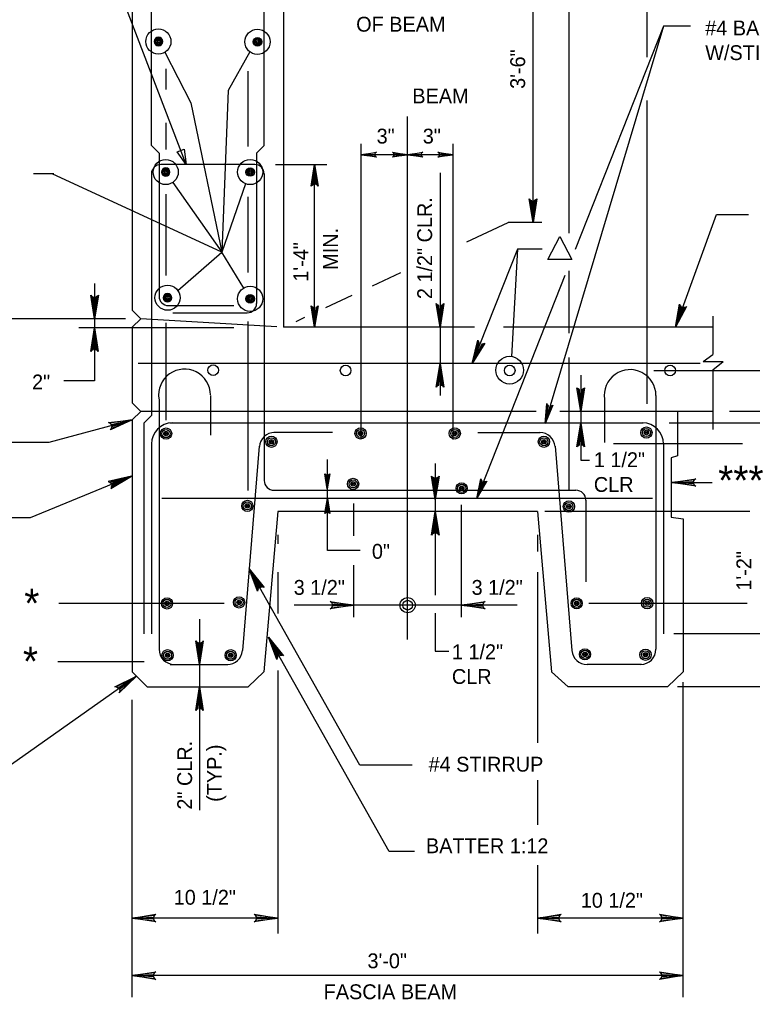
# Model space of a CAD drawing. Extents: x 642009 to 642864, y 298232 to 300014.
# Drawn here: x 642137.3 to 642285.5, y 298530.4 to 298728.5 of the extents above; entities that cross this region are included whole.
import ezdxf

# ---------------------------------------------------------------- set-up
doc = ezdxf.new("R2010")
doc.units = 0
for name, color, linetype in [('1', 7, 'Continuous'), ('15', 7, 'Continuous'), ('2', 7, 'Continuous'), ('22', 7, 'Continuous'), ('50', 7, 'Continuous')]:
    doc.layers.add(name, color=color, linetype=linetype)

# ---------------------------------------------------------------- blocks, each defined once
blk = doc.blocks.new('BAR')
at = {"layer": '50'}
for radius in [2, 1.5, 1, 0.5]:
    blk.add_circle((0, 0), radius, dxfattribs=at)

msp = doc.modelspace()

# ---------------------------------------------------------------- linework, layer by layer
at = {"layer": '1'}
for p, q in [((642227.71, 298683.59), (642236.08, 298687.5)), ((642237.99, 298682.07), (642228.8, 298659)), ((642237.99, 298682.07), (642236.75, 298660.42)), ((642208.66, 298674.71), (642214.36, 298677.37)), ((642199.22, 298670.31), (642204.57, 298672.8)), ((642193.2, 298667.5), (642195, 298668.34))]:
    msp.add_line(p, q, dxfattribs=at)
for points in [[(642241.68, 298692.04), (642241.35, 298691.87), (642241.11, 298687.5), (642241.68, 298692.04), (642241.87, 298692.27), (642241.11, 298687.5), (642240.89, 298691.86), (642240.56, 298692.02), (642241.11, 298687.5), (642240.35, 298692.27), (642240.56, 298692.02)], [(642153.04, 298672.57), (642152.71, 298672.41), (642152.47, 298668.03), (642153.04, 298672.57), (642153.24, 298672.81), (642152.47, 298668.03), (642152.25, 298672.4), (642151.93, 298672.56), (642152.47, 298668.03), (642151.71, 298672.81), (642151.93, 298672.56)], [(642222.89, 298670.85), (642222.56, 298670.68), (642222.32, 298666.31), (642222.89, 298670.85), (642223.09, 298671.09), (642222.32, 298666.31), (642222.1, 298670.68), (642221.78, 298670.84), (642222.32, 298666.31), (642221.56, 298671.09), (642221.78, 298670.84)], [(642151.9, 298661.65), (642152.23, 298661.81), (642152.47, 298666.19), (642151.9, 298661.65), (642151.7, 298661.41), (642152.47, 298666.19), (642152.69, 298661.82), (642153.01, 298661.66), (642152.47, 298666.19), (642153.23, 298661.41), (642153.01, 298661.66)], [(642231.11, 298662.95), (642230.74, 298662.92), (642228.8, 298659), (642231.11, 298662.95), (642231.38, 298663.08), (642228.8, 298659), (642230.32, 298663.1), (642230.08, 298663.37), (642228.8, 298659), (642229.98, 298663.69), (642230.08, 298663.37)], [(642221.75, 298654.46), (642222.08, 298654.63), (642222.32, 298659), (642221.75, 298654.46), (642221.55, 298654.23), (642222.32, 298659), (642222.53, 298654.63), (642222.86, 298654.47), (642222.32, 298659), (642223.08, 298654.23), (642222.86, 298654.47)], [(642251.32, 298653.85), (642250.99, 298653.68), (642250.75, 298649.31), (642251.32, 298653.85), (642251.52, 298654.09), (642250.75, 298649.31), (642250.53, 298653.68), (642250.21, 298653.84), (642250.75, 298649.31), (642249.99, 298654.09), (642250.21, 298653.84)], [(642250.18, 298642.37), (642250.51, 298642.53), (642250.75, 298646.91), (642250.18, 298642.37), (642249.98, 298642.13), (642250.75, 298646.91), (642250.96, 298642.54), (642251.29, 298642.38), (642250.75, 298646.91), (642251.51, 298642.13), (642251.29, 298642.38)], [(642155.92, 298633.96), (642155.95, 298634.33), (642159.91, 298636.21), (642155.92, 298633.96), (642155.78, 298633.69), (642159.91, 298636.21), (642155.78, 298634.75), (642155.51, 298634.99), (642159.91, 298636.21), (642155.2, 298635.1), (642155.51, 298634.99)], [(642221.92, 298636.01), (642221.59, 298635.84), (642221.35, 298631.47), (642221.92, 298636.01), (642222.12, 298636.24), (642221.35, 298631.47), (642221.14, 298635.84), (642220.81, 298636), (642221.35, 298631.47), (642220.59, 298636.24), (642220.81, 298636)], [(642273.76, 298634.36), (642273.59, 298634.69), (642269.22, 298634.93), (642273.76, 298634.36), (642273.99, 298634.16), (642269.22, 298634.93), (642273.58, 298635.15), (642273.74, 298635.47), (642269.22, 298634.93), (642273.99, 298635.69), (642273.74, 298635.47)], [(642220.78, 298624.52), (642221.11, 298624.69), (642221.35, 298629.06), (642220.78, 298624.52), (642220.58, 298624.29), (642221.35, 298629.06), (642221.57, 298624.69), (642221.89, 298624.54), (642221.35, 298629.06), (642222.11, 298624.29), (642221.89, 298624.54)], [(642185.48, 298613.26), (642185.68, 298613.56), (642183.75, 298617.49), (642185.48, 298613.26), (642185.42, 298612.96), (642183.75, 298617.49), (642186.08, 298613.79), (642186.44, 298613.81), (642183.75, 298617.49), (642186.75, 298613.71), (642186.44, 298613.81)], [(642200.35, 298610.7), (642200.52, 298610.38), (642204.89, 298610.13), (642200.35, 298610.7), (642200.11, 298610.9), (642204.89, 298610.13), (642200.52, 298609.92), (642200.36, 298609.59), (642204.89, 298610.13), (642200.11, 298609.38), (642200.36, 298609.59)], [(642231.18, 298609.56), (642231.01, 298609.89), (642226.64, 298610.13), (642231.18, 298609.56), (642231.41, 298609.36), (642226.64, 298610.13), (642231.01, 298610.35), (642231.17, 298610.68), (642226.64, 298610.13), (642231.41, 298610.89), (642231.17, 298610.68)], [(642189.37, 298599.45), (642189.58, 298599.76), (642187.64, 298603.69), (642189.37, 298599.45), (642189.31, 298599.15), (642187.64, 298603.69), (642189.97, 298599.99), (642190.33, 298600.01), (642187.64, 298603.69), (642190.64, 298599.9), (642190.33, 298600.01)], [(642174.26, 298602.67), (642173.93, 298602.5), (642173.69, 298598.13), (642174.26, 298602.67), (642174.46, 298602.9), (642173.69, 298598.13), (642173.48, 298602.49), (642173.15, 298602.65), (642173.69, 298598.13), (642172.94, 298602.9), (642173.15, 298602.65)], [(642156.91, 298593.6), (642157.23, 298593.43), (642160.94, 298595.76), (642156.91, 298593.6), (642156.6, 298593.63), (642160.94, 298595.76), (642157.5, 298593.06), (642157.56, 298592.7), (642160.94, 298595.76), (642157.48, 298592.38), (642157.56, 298592.7)], [(642173.12, 298589.08), (642173.45, 298589.25), (642173.69, 298593.63), (642173.12, 298589.08), (642172.92, 298588.85), (642173.69, 298593.63), (642173.91, 298589.26), (642174.23, 298589.1), (642173.69, 298593.63), (642174.45, 298588.85), (642174.23, 298589.1)], [(642164.62, 298546.31), (642164.45, 298546.64), (642160.08, 298546.88), (642164.62, 298546.31), (642164.85, 298546.11), (642160.08, 298546.88), (642164.44, 298547.09), (642164.6, 298547.42), (642160.08, 298546.88), (642164.85, 298547.64), (642164.6, 298547.42)], [(642184.97, 298547.45), (642185.14, 298547.12), (642189.51, 298546.88), (642184.97, 298547.45), (642184.74, 298547.65), (642189.51, 298546.88), (642185.15, 298546.66), (642184.99, 298546.34), (642189.51, 298546.88), (642184.74, 298546.12), (642184.99, 298546.34)], [(642246.55, 298546.31), (642246.38, 298546.64), (642242.01, 298546.88), (642246.55, 298546.31), (642246.79, 298546.11), (642242.01, 298546.88), (642246.38, 298547.09), (642246.54, 298547.42), (642242.01, 298546.88), (642246.79, 298547.64), (642246.54, 298547.42)], [(642266.91, 298547.45), (642267.08, 298547.12), (642271.45, 298546.88), (642266.91, 298547.45), (642266.68, 298547.65), (642271.45, 298546.88), (642267.08, 298546.66), (642266.92, 298546.34), (642271.45, 298546.88), (642266.68, 298546.12), (642266.92, 298546.34)], [(642164.62, 298534.67), (642164.45, 298535), (642160.08, 298535.24), (642164.62, 298534.67), (642164.85, 298534.47), (642160.08, 298535.24), (642164.44, 298535.46), (642164.6, 298535.78), (642160.08, 298535.24), (642164.85, 298536), (642164.6, 298535.78)], [(642266.91, 298535.81), (642267.08, 298535.48), (642271.45, 298535.24), (642266.91, 298535.81), (642266.68, 298536.01), (642271.45, 298535.24), (642267.08, 298535.02), (642266.92, 298534.7), (642271.45, 298535.24), (642266.68, 298534.48), (642266.92, 298534.7)]]:
    msp.add_lwpolyline(points, dxfattribs=at)
msp.add_lwpolyline([(642244.11, 298679.99), (642246.52, 298684.68), (642248.93, 298679.99)], close=True, dxfattribs=at)
for centre, radius in [((642165.38, 298724.07), 2.54), ((642185.4, 298724.02), 2.54), ((642166.86, 298697.69), 2.54), ((642183.93, 298697.69), 2.54), ((642167.23, 298672.28), 2.54), ((642183.93, 298672.06), 2.54), ((642236.39, 298657.64), 2.8), ((642176.44, 298657.64), 1.08), ((642203.23, 298657.57), 1.08), ((642236.4, 298657.57), 1.08), ((642268.82, 298657.57), 1.08), ((642215.76, 298610.13), 1.53), ((642215.76, 298610.13), 0.983)]:
    msp.add_circle(centre, radius, dxfattribs=at)
at = {"layer": '15'}
for p, q in [((642165.5, 298651.76), (642165.5, 298601.22)), ((642265.96, 298652.52), (642265.96, 298601.22)), ((642162.43, 298646.92), (642163.97, 298648.49)), ((642162.43, 298646.92), (642162.43, 298604.35))]:
    msp.add_line(p, q, dxfattribs=at)
at = {"layer": '2'}
for p, q in [((642160.07, 298771.67), (642160.07, 298669.76)), ((642190.65, 298771.5), (642190.65, 298666.31)), ((642163.97, 298703.05), (642163.97, 298767.05)), ((642186.76, 298703.05), (642186.76, 298767.05)), ((642264.14, 298750.64), (642264.14, 298720.9)), ((642170.97, 298699.21), (642153.94, 298743.88)), ((642248.32, 298738.81), (642248.32, 298685.35)), ((642241.11, 298687.5), (642241.11, 298731.74)), ((642267.51, 298727.19), (642243.99, 298648.41)), ((642267.51, 298727.19), (642249.64, 298682)), ((642272.91, 298727.19), (642267.51, 298727.19)), ((642166.86, 298718.54), (642166.86, 298714.37)), ((642183.48, 298718.11), (642183.48, 298702.86)), ((642264.14, 298712.16), (642264.14, 298650.83)), ((642215.76, 298603.21), (642215.76, 298708.92)), ((642166.86, 298707.65), (642166.86, 298702.26)), ((642160.08, 298705.6), (642160.08, 298669.76)), ((642163.97, 298703.05), (642165.5, 298701.51)), ((642186.76, 298703.05), (642185.22, 298701.51)), ((642206.39, 298643.89), (642206.39, 298703.41)), ((642224.95, 298643.59), (642224.95, 298703.41)), ((642165.5, 298701.51), (642165.5, 298672.58)), ((642185.22, 298701.51), (642185.22, 298671.12)), ((642206.39, 298701.2), (642206.39, 298701.2)), ((642224.95, 298701.2), (642206.39, 298701.2)), ((642224.95, 298701.2), (642224.95, 298701.2)), ((642189.04, 298699.21), (642199.45, 298699.21)), ((642196.96, 298666.31), (642196.96, 298699.21)), ((642144.27, 298697.32), (642140.14, 298697.32)), ((642178.17, 298681.46), (642143.87, 298697.32)), ((642163.97, 298697.32), (642163.97, 298648.49)), ((642186.76, 298697.32), (642186.76, 298635.36)), ((642222.32, 298697.51), (642222.32, 298652.52)), ((642168.29, 298695.59), (642178.17, 298681.46)), ((642183, 298695.32), (642178.17, 298681.46)), ((642166.86, 298693.22), (642166.86, 298676.78)), ((642183.48, 298692.67), (642183.48, 298677.38)), ((642270.77, 298668.68), (642278.18, 298689.08)), ((642278.18, 298689.08), (642284.67, 298689.08)), ((642242.87, 298687.5), (642236.08, 298687.5)), ((642169.32, 298673.74), (642178.17, 298681.46)), ((642182.63, 298674.24), (642178.17, 298681.46)), ((642242.96, 298682.07), (642237.99, 298682.07)), ((642248.32, 298677.74), (642248.32, 298665.12)), ((642152.47, 298675.18), (642152.47, 298655.51)), ((642247.57, 298676.77), (642229.76, 298631.7)), ((642160.08, 298669.76), (642161.8, 298668.03)), ((642167.38, 298670.7), (642180.64, 298670.7)), ((642168.27, 298669.24), (642183.34, 298669.24)), ((642158.72, 298668.03), (642082.96, 298668.03)), ((642161.8, 298668.03), (642160.08, 298666.31)), ((642189.3, 298666.39), (642161.8, 298668.03)), ((642166.86, 298667.18), (642166.86, 298647.55)), ((642183.48, 298667.48), (642183.48, 298633.32)), ((642277.44, 298668.56), (642277.44, 298660.8)), ((642180.64, 298666.19), (642149.32, 298666.19)), ((642160.08, 298666.31), (642160.08, 298651.03)), ((642229.31, 298666.31), (642190.65, 298666.31)), ((642277.44, 298666.31), (642235.17, 298666.31)), ((642248.32, 298660.21), (642248.32, 298633.32)), ((642275.47, 298659.41), (642277.47, 298660.8)), ((642275.47, 298659.41), (642279.53, 298659.41)), ((642277.47, 298657.73), (642279.53, 298659.41)), ((642274.89, 298659), (642161.32, 298659)), ((642297.41, 298657.5), (642265.51, 298657.5)), ((642277.44, 298657.73), (642277.44, 298645.67)), ((642152.47, 298655.51), (642146.24, 298655.51)), ((642250.75, 298656.64), (642250.75, 298646.91)), ((642175.9, 298652.52), (642175.9, 298644.51)), ((642255.56, 298651.76), (642255.56, 298642.99)), ((642160.08, 298651.03), (642161.8, 298649.31)), ((642161.8, 298649.31), (642160.08, 298647.59)), ((642241.74, 298649.31), (642161.8, 298649.31)), ((642277.44, 298649.31), (642246.53, 298649.31)), ((642270.33, 298649.31), (642270.33, 298640.31)), ((642335.23, 298649.31), (642280.82, 298649.31)), ((642160.08, 298647.59), (642160.08, 298596.63)), ((642263.39, 298646.91), (642167.71, 298646.91)), ((642250.75, 298646.91), (642250.75, 298639.46)), ((642288.58, 298646.91), (642268.61, 298646.91)), ((642200.56, 298645.03), (642188.72, 298645.03)), ((642229.96, 298645.03), (642242.52, 298645.03)), ((642163.97, 298642.73), (642163.97, 298604.35)), ((642185.78, 298642.26), (642182.39, 298600.94)), ((642245.56, 298642.28), (642248.95, 298600.94)), ((642283.43, 298642.72), (642257.39, 298642.72)), ((642267.49, 298642.73), (642267.49, 298604.35)), ((642199.55, 298630.71), (642199.55, 298639.58)), ((642270.33, 298640.31), (642269.01, 298639.94)), ((642269.01, 298639.94), (642269.01, 298627.94)), ((642221.35, 298638.8), (642221.35, 298629.06)), ((642159.91, 298636.21), (642139.47, 298627.77)), ((642188.76, 298633.36), (642249.78, 298633.36)), ((642269.22, 298634.93), (642277.29, 298634.93)), ((642251.78, 298631.36), (642251.78, 298614.83)), ((642199.55, 298621.16), (642199.55, 298630.71)), ((642204.89, 298624.14), (642204.89, 298630.69)), ((642226.64, 298624.69), (642226.64, 298630.39)), ((642139.47, 298627.77), (642092.33, 298627.77)), ((642189.51, 298629.06), (642186.7, 298596.63)), ((642242.01, 298629.06), (642189.51, 298629.06)), ((642221.35, 298629.06), (642221.35, 298612.14)), ((642242.01, 298629.06), (642244.83, 298596.63)), ((642284.92, 298629.06), (642243.49, 298629.06)), ((642269.01, 298627.94), (642271.45, 298627.56)), ((642271.45, 298627.56), (642271.45, 298596.63)), ((642189.51, 298624.38), (642189.51, 298622.51)), ((642226.64, 298607.7), (642226.64, 298624.69)), ((642242.01, 298624.38), (642242.01, 298621.01)), ((642206.19, 298621.16), (642199.55, 298621.16)), ((642204.89, 298607.7), (642204.89, 298618.2)), ((642206.12, 298577.78), (642183.75, 298617.49)), ((642189.51, 298616.81), (642189.51, 298608.44)), ((642242.01, 298616.81), (642242.01, 298582.3)), ((642178.64, 298610.5), (642145.26, 298610.5)), ((642204.89, 298610.13), (642192.83, 298610.13)), ((642215.76, 298610.13), (642204.89, 298610.13)), ((642226.64, 298610.13), (642215.76, 298610.13)), ((642237.91, 298610.13), (642226.64, 298610.13)), ((642273.33, 298610.5), (642252.4, 298610.5)), ((642284.39, 298610.5), (642272.2, 298610.5)), ((642221.35, 298608.54), (642221.35, 298600.81)), ((642173.69, 298607.32), (642173.69, 298598.13)), ((642212.05, 298560.36), (642187.64, 298603.69)), ((642288.71, 298604.31), (642269.55, 298604.31)), ((642162.49, 298598.69), (642145.04, 298598.69)), ((642167.76, 298598.13), (642179.39, 298598.13)), ((642173.69, 298598.13), (642173.69, 298593.63)), ((642263.01, 298598.12), (642252.03, 298598.12)), ((642160.94, 298595.76), (642135.66, 298577.9)), ((642160.08, 298596.63), (642163.08, 298593.63)), ((642186.7, 298596.63), (642183.52, 298593.63)), ((642189.51, 298596.89), (642189.51, 298543.75)), ((642244.83, 298596.63), (642248.2, 298593.63)), ((642271.45, 298596.63), (642268.26, 298593.63)), ((642271.45, 298530.86), (642271.45, 298594.56)), ((642163.08, 298593.63), (642183.52, 298593.63)), ((642173.69, 298593.63), (642173.69, 298568.68)), ((642268.26, 298593.63), (642248.2, 298593.63)), ((642335.31, 298593.63), (642270.33, 298593.63)), ((642160.08, 298530.86), (642160.08, 298591.02)), ((642216.7, 298577.78), (642206.12, 298577.78)), ((642242.01, 298574.73), (642242.01, 298565.75)), ((642217.13, 298560.36), (642212.05, 298560.36)), ((642242.01, 298557.58), (642242.01, 298543.75)), ((642189.51, 298546.88), (642160.08, 298546.88)), ((642271.45, 298546.88), (642242.01, 298546.88)), ((642271.45, 298535.24), (642160.08, 298535.24))]:
    msp.add_line(p, q, dxfattribs=at)
for points in [[(642166.69, 298721.89), (642171.93, 298711.71), (642178.17, 298681.46)], [(642183.84, 298722.01), (642179.45, 298714.18), (642178.17, 298681.46)], [(642209.29, 298700.83), (642209.19, 298701.04), (642206.39, 298701.2), (642209.29, 298700.83), (642209.44, 298700.7), (642206.39, 298701.2), (642209.18, 298701.33), (642209.29, 298701.54), (642206.39, 298701.2), (642209.44, 298701.68), (642209.29, 298701.54)], [(642212.86, 298701.56), (642212.96, 298701.35), (642215.76, 298701.2), (642212.86, 298701.56), (642212.71, 298701.69), (642215.76, 298701.2), (642212.97, 298701.06), (642212.86, 298700.85), (642215.76, 298701.2), (642212.71, 298700.71), (642212.86, 298700.85)], [(642218.67, 298700.83), (642218.56, 298701.04), (642215.76, 298701.2), (642218.67, 298700.83), (642218.82, 298700.7), (642215.76, 298701.2), (642218.56, 298701.33), (642218.66, 298701.54), (642215.76, 298701.2), (642218.82, 298701.68), (642218.66, 298701.54)], [(642222.04, 298701.56), (642222.15, 298701.35), (642224.95, 298701.2), (642222.04, 298701.56), (642221.89, 298701.69), (642224.95, 298701.2), (642222.15, 298701.06), (642222.05, 298700.85), (642224.95, 298701.2), (642221.89, 298700.71), (642222.05, 298700.85)], [(642184.87, 298699.21), (642165.85, 298699.21)], [(642196.43, 298695.05), (642196.73, 298695.21), (642196.96, 298699.21), (642196.43, 298695.05), (642196.25, 298694.84), (642196.96, 298699.21), (642197.15, 298695.21), (642197.45, 298695.07), (642196.96, 298699.21), (642197.65, 298694.84), (642197.45, 298695.07)], [(642197.48, 298670.46), (642197.18, 298670.31), (642196.95, 298666.31), (642197.48, 298670.46), (642197.66, 298670.67), (642196.95, 298666.31), (642196.76, 298670.3), (642196.46, 298670.45), (642196.95, 298666.31), (642196.26, 298670.67), (642196.46, 298670.45)], [(642271.88, 298670.33), (642271.52, 298670.28), (642269.91, 298666.31), (642271.88, 298670.33), (642272.13, 298670.48), (642269.91, 298666.31), (642271.1, 298670.42), (642270.84, 298670.67), (642269.91, 298666.31), (642270.72, 298670.96), (642270.84, 298670.67)], [(642244.9, 298650.43), (642244.6, 298650.35), (642243.53, 298646.87), (642244.9, 298650.43), (642245.1, 298650.57), (642243.53, 298646.87), (642244.23, 298650.44), (642243.99, 298650.64), (642243.53, 298646.87), (642243.87, 298650.88), (642243.99, 298650.64)], [(642199.89, 298636.53), (642199.68, 298636.42), (642199.52, 298633.63), (642199.89, 298636.53), (642200.01, 298636.68), (642199.52, 298633.63), (642199.38, 298636.42), (642199.18, 298636.52), (642199.52, 298633.63), (642199.04, 298636.68), (642199.18, 298636.52)], [(642231.54, 298635.07), (642231.23, 298635.03), (642229.76, 298631.7), (642231.54, 298635.07), (642231.76, 298635.19), (642229.76, 298631.7), (642230.87, 298635.16), (642230.67, 298635.38), (642229.76, 298631.7), (642230.57, 298635.64), (642230.67, 298635.38)], [(642199.18, 298628.79), (642199.39, 298628.9), (642199.55, 298631.7), (642199.18, 298628.79), (642199.05, 298628.64), (642199.55, 298631.7), (642199.68, 298628.9), (642199.89, 298628.8), (642199.55, 298631.7), (642200.03, 298628.64), (642199.89, 298628.8)]]:
    msp.add_lwpolyline(points, dxfattribs=at)
msp.add_lwpolyline([(642170.6, 298702.31), (642170.97, 298699.21), (642169.18, 298701.77)], close=True, dxfattribs=at)
for centre, radius in [((642166.92, 298644.81), 1.14), ((642166.92, 298644.81), 0.817), ((642166.92, 298644.81), 0.447), ((642206.24, 298644.85), 1.14), ((642206.24, 298644.85), 0.817), ((642206.24, 298644.85), 0.447), ((642225.29, 298644.85), 1.14), ((642225.29, 298644.85), 0.817), ((642225.29, 298644.85), 0.447), ((642264.03, 298645.03), 1.14), ((642264.03, 298645.03), 0.817), ((642264.03, 298645.03), 0.447), ((642264.03, 298645.03), 0.225), ((642166.92, 298644.81), 0.225), ((642166.92, 298644.81), 0.0966), ((642188.22, 298643.16), 1.14), ((642188.22, 298643.16), 0.817), ((642188.22, 298643.16), 0.447), ((642188.22, 298643.16), 0.225), ((642188.22, 298643.16), 0.0966), ((642206.24, 298644.85), 0.225), ((642206.24, 298644.85), 0.0966), ((642225.29, 298644.85), 0.225), ((642225.29, 298644.85), 0.0966), ((642243.31, 298643.16), 1.14), ((642243.31, 298643.16), 0.817), ((642243.31, 298643.16), 0.447), ((642243.31, 298643.16), 0.225), ((642243.31, 298643.16), 0.0966), ((642264.03, 298645.03), 0.0966), ((642204.74, 298634.65), 1.14), ((642204.74, 298634.65), 0.817), ((642204.74, 298634.65), 0.447), ((642204.74, 298634.65), 0.225), ((642204.74, 298634.65), 0.0966), ((642226.68, 298633.75), 1.14), ((642226.68, 298633.75), 0.817), ((642226.68, 298633.75), 0.447), ((642226.68, 298633.75), 0.225), ((642226.68, 298633.75), 0.0966), ((642183.36, 298630.19), 1.14), ((642183.36, 298630.19), 0.817), ((642183.36, 298630.19), 0.447), ((642183.36, 298630.19), 0.225), ((642183.36, 298630.19), 0.0966), ((642248.36, 298630.08), 1.14), ((642248.36, 298630.08), 0.817), ((642248.36, 298630.08), 0.447), ((642248.36, 298630.08), 0.225), ((642248.36, 298630.08), 0.0966), ((642167.12, 298610.49), 1.14), ((642181.68, 298610.69), 1.14), ((642249.93, 298610.5), 1.14), ((642264.18, 298610.53), 1.14), ((642167.12, 298610.49), 0.817), ((642167.12, 298610.49), 0.447), ((642167.12, 298610.49), 0.225), ((642167.12, 298610.49), 0.0966), ((642181.68, 298610.69), 0.817), ((642181.68, 298610.69), 0.447), ((642181.68, 298610.69), 0.225), ((642181.68, 298610.69), 0.0966), ((642249.93, 298610.5), 0.817), ((642249.93, 298610.5), 0.447), ((642249.93, 298610.5), 0.225), ((642249.93, 298610.5), 0.0966), ((642264.18, 298610.53), 0.817), ((642264.18, 298610.53), 0.447), ((642264.18, 298610.53), 0.225), ((642264.18, 298610.53), 0.0966), ((642167.24, 298600), 1.14), ((642167.24, 298600), 0.817), ((642167.24, 298600), 0.447), ((642167.24, 298600), 0.225), ((642167.24, 298600), 0.0966), ((642179.99, 298600), 1.14), ((642179.99, 298600), 0.817), ((642179.99, 298600), 0.447), ((642179.99, 298600), 0.225), ((642179.99, 298600), 0.0966), ((642251.61, 298600.19), 1.14), ((642251.61, 298600.19), 0.817), ((642251.61, 298600.19), 0.447), ((642251.61, 298600.19), 0.225), ((642251.61, 298600.19), 0.0966), ((642263.84, 298600.11), 1.14), ((642263.84, 298600.11), 0.817), ((642263.84, 298600.11), 0.447), ((642263.84, 298600.11), 0.225), ((642263.84, 298600.11), 0.0966)]:
    msp.add_circle(centre, radius, dxfattribs=at)
for centre, radius, start, end in [((642165.85, 298697.32), 1.88, 90, 180), ((642184.87, 298697.32), 1.88, 0, 90), ((642167.38, 298672.58), 1.88, 180, 270), ((642183.34, 298671.12), 1.88, 270, 0), ((642170.65, 298652.62), 5.23, 0, 188.3783), ((642260.73, 298652.52), 5.23, 0, 188.3783), ((642168.22, 298642.73), 4.25, 90, 180), ((642263.24, 298642.73), 4.25, 0, 90), ((642188.87, 298641.94), 3.09, 90, 175.2381), ((642242.49, 298641.93), 3.09, 4.7619, 90), ((642188.76, 298635.36), 2, 180, 270), ((642249.78, 298631.36), 2, 0, 90), ((642168.6, 298601.22), 3.09, 180, 270), ((642179.3, 298601.22), 3.09, 270, 355.2392), ((642252.03, 298601.21), 3.09, 184.7608, 270), ((642262.86, 298601.22), 3.09, 270, 0)]:
    msp.add_arc(centre, radius, start, end, dxfattribs=at)
at = {"layer": '22'}
for p, q in [((642143.31, 298643.09), (642160.08, 298647.59)), ((642075.63, 298643.09), (642143.31, 298643.09)), ((642250.75, 298639.46), (642252.53, 298639.46)), ((642265.26, 298631.7), (642166.08, 298631.7)), ((642221.35, 298600.81), (642224.1, 298600.81))]:
    msp.add_line(p, q, dxfattribs=at)
msp.add_lwpolyline([(642155.55, 298646.92), (642155.8, 298646.65), (642160.08, 298647.59), (642155.55, 298646.92), (642155.27, 298647.05), (642160.08, 298647.59), (642155.93, 298646.21), (642155.86, 298645.85), (642160.08, 298647.59), (642155.68, 298645.58), (642155.86, 298645.85)], dxfattribs=at)

# ---------------------------------------------------------------- block references
at = {"layer": '2', "xscale": 0.4303528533, "yscale": -0.4303528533, "rotation": 180}
for p in [(642165.38, 298724.07), (642166.86, 298697.69), (642167.23, 298672.28)]:
    msp.add_blockref('BAR', p, dxfattribs=at)
at = {"layer": '2', "xscale": 0.4303528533, "yscale": 0.4303528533}
for p in [(642185.4, 298724.02), (642183.93, 298697.69), (642183.93, 298672.06)]:
    msp.add_blockref('BAR', p, dxfattribs=at)

# ---------------------------------------------------------------- texts
at = {"layer": '2'}
for s, height, p in [('OF BEAM', 3, (642205.36, 298726.07)), ('#4 BAR, MATCH', 3, (642275.92, 298725.32)), ('W/STIRRUP', 3, (642275.92, 298720.32)), ('  BEAM', 3, (642214.48, 298711.57)), ('3"', 3, (642209.49, 298703.45)), ('3"', 3, (642218.82, 298703.45)), ('2"', 3, (642139.84, 298653.75)), ('***', 5.88, (642278.53, 298632.43)), ('0"', 3, (642208.54, 298619.51)), ('3 1/2"', 3, (642192.73, 298612.22)), ('3 1/2"', 3, (642228.69, 298612.22)), ('*', 5.88, (642138.26, 298607.59)), ('*', 5.88, (642137.99, 298595.85)), ('#4 STIRRUP', 3, (642220, 298576.48)), ('BATTER 1:12', 3, (642219.47, 298559.99)), ('10 1/2"', 3, (642168.47, 298549.58)), ('10 1/2"', 3, (642250.76, 298548.97)), ('3\'-0"', 3, (642207.64, 298536.73)), ('FASCIA BEAM', 3, (642198.79, 298530.48))]:
    msp.add_text(s, height=height, dxfattribs=at).set_placement(p)
for s, p in [('3\'-6"', (642239.51, 298714.5)), ('2 1/2" CLR.', (642220.71, 298672)), ('MIN.', (642201.68, 298677.92)), ('1\'-4"', (642195.66, 298675.52)), ('1\'-2"', (642285.23, 298613.07)), ('2" CLR.', (642172.19, 298568.8)), ('(TYP.)', (642178.19, 298570.37))]:
    msp.add_text(s, height=3, rotation=90, dxfattribs=at).set_placement(p)
at = {"layer": '22'}
for s, p in [('1 1/2"', (642253.4, 298638.03)), ('CLR', (642253.4, 298633.03)), ('1 1/2"', (642224.71, 298599.21)), ('CLR', (642224.71, 298594.21))]:
    msp.add_text(s, height=3, dxfattribs=at).set_placement(p)

doc.saveas('drawing.dxf')
